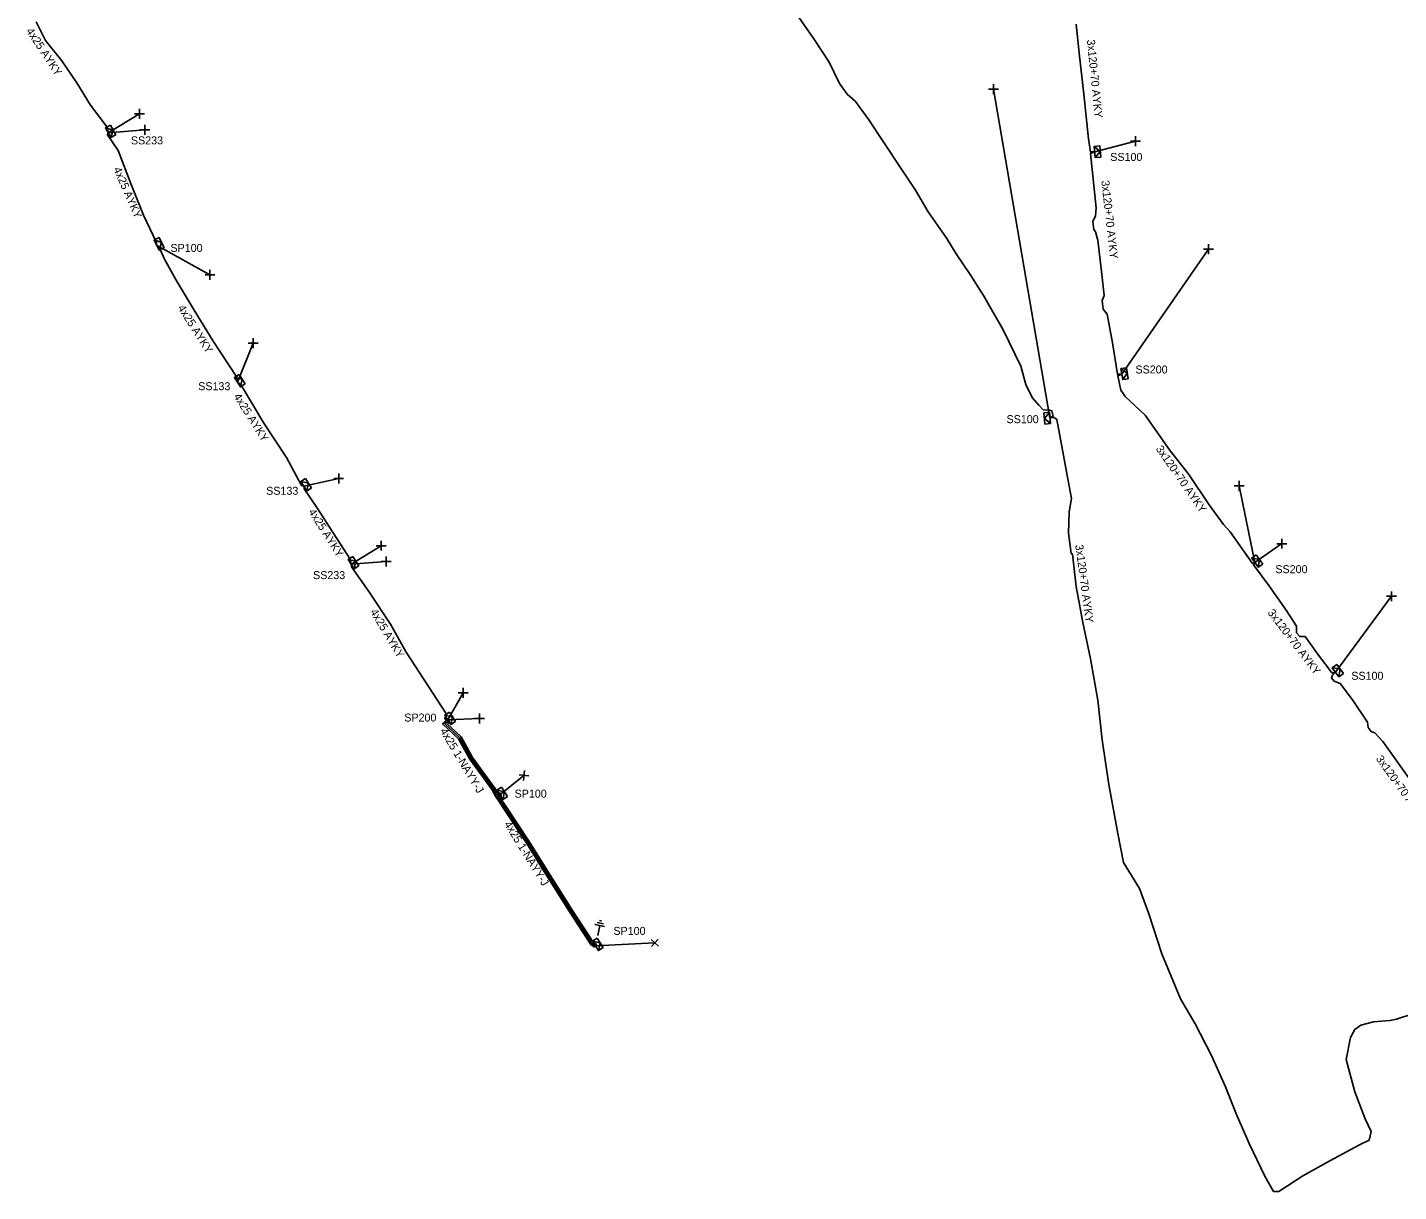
# Model space of a CAD drawing. Extents: x -763093 to -760976, y -1155572 to -1152009.
# Drawn here: x -762615.5 to -762444.1, y -1155221.8 to -1155076.3 of the extents above; entities that cross this region are included whole.
import ezdxf

# ---------------------------------------------------------------- set-up
doc = ezdxf.new("R2010")
doc.units = 0
for name, color, linetype in [('Vrstva 1', 7, 'Continuous'), ('Vrstva 14', 7, 'Continuous'), ('Vrstva 15', 7, 'Continuous'), ('Vrstva 20', 7, 'Continuous'), ('Vrstva 31', 7, 'Continuous'), ('Vrstva 33', 7, 'Continuous'), ('Vrstva 34', 7, 'Continuous'), ('Vrstva 5', 7, 'Continuous'), ('Vrstva 59', 7, 'Continuous'), ('Vrstva 6', 7, 'Continuous'), ('Vrstva 9', 7, 'Continuous')]:
    doc.layers.add(name, color=color, linetype=linetype)

# ---------------------------------------------------------------- blocks, each defined once
blk = doc.blocks.new('NN800')
at = {"layer": 'Vrstva 1'}
for points in [[(-0.44, 0.44), (0.44, -0.44)], [(-0.44, -0.44), (0.44, 0.44)]]:
    blk.add_lwpolyline(points, dxfattribs=at)
blk = doc.blocks.new('NN630')
at = {"layer": 'Vrstva 9'}
for points in [[(0, -0.7), (-0.7, 0)], [(-0.7, -0.7), (-0.7, 0), (0.7, 0), (0.7, -0.7)], [(-0.7, -0.7), (0.7, -0.7)], [(0, -0.7), (0.7, 0)]]:
    blk.add_lwpolyline(points, dxfattribs=at)
blk = doc.blocks.new('NN810')
at = {"layer": 'Vrstva 14'}
for points in [[(0, -0.64), (0, -1.89)], [(0.63, -1.89), (-0.62, -1.89)], [(0.39, -2.2), (-0.4, -2.2)], [(0, -2.52), (-0.12, -2.52)], [(0.14, -2.52), (0, -2.52)]]:
    blk.add_lwpolyline(points, dxfattribs=at)

msp = doc.modelspace()

# ---------------------------------------------------------------- linework, layer by layer
at = {"layer": 'Vrstva 20'}
for points in [[(-762556.36, -1155172.02), (-762556.52, -1155172.38), (-762556.7, -1155172.3), (-762556.93, -1155172.42), (-762557.4, -1155171.57), (-762560.19, -1155167.73), (-762561.58, -1155165.2), (-762562.83, -1155164.02), (-762563.58, -1155163.32), (-762563.16, -1155162.97), (-762563.15, -1155162.79), (-762562.75, -1155162.83), (-762562.78, -1155163.18), (-762562.97, -1155163.34), (-762562.56, -1155163.73), (-762561.26, -1155164.95), (-762559.85, -1155167.51), (-762557.06, -1155171.35), (-762556.76, -1155171.88), (-762556.71, -1155171.86)], [(-762544.58, -1155191.22), (-762545.05, -1155190.9), (-762547.77, -1155186.73), (-762550.88, -1155181.78), (-762553.07, -1155178.26), (-762556.01, -1155173.82), (-762556.61, -1155172.9), (-762556.87, -1155172.52), (-762556.64, -1155172.39), (-762556.64, -1155172.2), (-762556.24, -1155172.2), (-762556.24, -1155172.63), (-762556.29, -1155172.66), (-762556.28, -1155172.68), (-762555.67, -1155173.6), (-762552.74, -1155178.04), (-762550.54, -1155181.57), (-762547.44, -1155186.51), (-762544.76, -1155190.62), (-762544.35, -1155190.89)]]:
    msp.add_lwpolyline(points, close=True, dxfattribs=at)
at = {"layer": 'Vrstva 5'}
for points in [[(-762440.3, -1155198.87), (-762444.38, -1155200.23), (-762445.2, -1155200.39), (-762447.26, -1155200.56), (-762448.82, -1155200.98), (-762449.57, -1155201.5), (-762450.15, -1155202.53), (-762450.66, -1155205.25), (-762449.57, -1155209.31), (-762448.28, -1155212.66), (-762447.55, -1155214.26), (-762447.82, -1155215.36), (-762449, -1155215.91), (-762452.72, -1155217.93), (-762456.07, -1155219.81), (-762459.07, -1155221.77), (-762459.74, -1155221.74), (-762460.84, -1155219.85), (-762462.81, -1155215.76), (-762464.36, -1155212.15), (-762465.77, -1155208.66), (-762467.51, -1155204.77), (-762469.53, -1155200.8), (-762471.39, -1155197.67), (-762473.7, -1155192.06), (-762475.32, -1155187.04), (-762476.49, -1155183.9), (-762478.48, -1155180.65), (-762479.2, -1155177.03), (-762480.33, -1155170.91), (-762481.18, -1155165.31), (-762481.72, -1155160.37), (-762482.61, -1155155.2), (-762483.59, -1155150.64), (-762484.4, -1155146.14), (-762484.87, -1155142.1), (-762485.04, -1155142.02), (-762485.38, -1155139.5), (-762485.29, -1155136.83), (-762484.99, -1155135.17), (-762485.6, -1155131.81), (-762486.17, -1155128.88), (-762486.83, -1155125.28), (-762487.16, -1155125.05), (-762487.69, -1155125.08), (-762487.29, -1155124.87), (-762487.44, -1155124.21), (-762487.85, -1155124.07), (-762488.49, -1155124.1), (-762489.07, -1155123.5), (-762489.9, -1155122.54), (-762490.68, -1155120.9), (-762491.31, -1155118.62), (-762493.55, -1155114.08), (-762495.99, -1155109.77), (-762497.67, -1155107.14), (-762499.39, -1155104.57), (-762500.55, -1155102.67), (-762502.92, -1155099.32), (-762504.49, -1155096.63), (-762506.42, -1155093.74), (-762510.32, -1155087.83), (-762512, -1155085.56), (-762513.01, -1155084.64), (-762514, -1155083.29), (-762515.27, -1155080.61), (-762517.19, -1155077.69), (-762519.67, -1155074.14)], [(-762614.37, -1155075.57), (-762613.2, -1155077.93), (-762611.17, -1155080.46), (-762609.28, -1155083.2), (-762607.58, -1155085.98), (-762605.5, -1155088.73), (-762605.36, -1155089.44), (-762605.45, -1155089.72), (-762604.11, -1155091.68), (-762602.49, -1155095.92), (-762600.94, -1155099.73), (-762599.33, -1155103.18), (-762599.31, -1155103.48), (-762598.86, -1155104.05), (-762598.33, -1155105.25), (-762596.85, -1155107.87), (-762594.6, -1155111.6), (-762592.25, -1155115.5), (-762589.3, -1155120), (-762589.21, -1155120.62), (-762588.75, -1155120.99), (-762585.91, -1155125.73), (-762583.08, -1155130.03), (-762581.2, -1155133.52), (-762580.92, -1155133.62), (-762580.88, -1155133.96), (-762579.31, -1155136.29), (-762577.27, -1155139.43), (-762575.13, -1155142.75), (-762574.99, -1155143.36), (-762574.94, -1155143.69), (-762572.79, -1155146.79), (-762570.07, -1155150.85), (-762568.12, -1155154.36), (-762563.09, -1155162.11), (-762563.3, -1155162.67), (-762562.94, -1155162.81)], [(-762452, -1155156.87), (-762452.41, -1155157), (-762454.12, -1155154.73), (-762455.8, -1155152.38), (-762456.47, -1155152.42), (-762456.87, -1155151.96), (-762456.9, -1155151.12), (-762458.15, -1155149.1), (-762460.34, -1155146.01), (-762462.24, -1155143.44), (-762462.07, -1155143.17), (-762462.36, -1155143.28), (-762465.15, -1155139.3), (-762466.01, -1155138.41), (-762467.8, -1155135.94), (-762470.34, -1155132.16), (-762472.74, -1155129.06), (-762475.78, -1155124.73), (-762478.24, -1155122.46), (-762478.83, -1155121.6), (-762479.21, -1155119.82), (-762478.71, -1155119.61), (-762479.25, -1155119.62), (-762479.85, -1155115.7), (-762480.54, -1155112.1), (-762481.04, -1155111.49), (-762481.18, -1155110.43), (-762480.91, -1155109.77), (-762481.24, -1155106.79), (-762481.69, -1155102.88), (-762482, -1155101.82), (-762482.22, -1155101.52), (-762482.31, -1155100.55), (-762482.01, -1155099.84), (-762481.9, -1155098.84), (-762482.62, -1155092.05), (-762482.09, -1155091.85), (-762482.64, -1155091.85), (-762482.88, -1155090.2), (-762483.46, -1155084.63), (-762484.04, -1155079.48), (-762484.39, -1155075.89)], [(-762452, -1155156.87), (-762452.4, -1155157.22), (-762452.5, -1155157.55), (-762452.19, -1155158), (-762451.44, -1155158.29), (-762449.88, -1155160.3), (-762448, -1155163.1), (-762447.93, -1155163.76), (-762447.55, -1155164.29), (-762447.11, -1155164.46), (-762446.11, -1155165.54), (-762442.69, -1155170.32), (-762439.62, -1155174.75), (-762438.62, -1155175.88), (-762438.38, -1155175.68)], [(-762562.95, -1155162.81), (-762562.97, -1155163.08), (-762563.28, -1155163.33), (-762562.69, -1155163.88), (-762561.42, -1155165.08), (-762560.02, -1155167.62), (-762557.23, -1155171.46), (-762556.84, -1155172.15), (-762556.71, -1155172.08), (-762556.44, -1155172.2), (-762556.44, -1155172.51), (-762556.58, -1155172.59), (-762556.45, -1155172.79), (-762555.84, -1155173.71), (-762552.91, -1155178.15), (-762550.71, -1155181.68), (-762547.61, -1155186.62), (-762544.91, -1155190.76), (-762544.47, -1155191.06)]]:
    msp.add_lwpolyline(points, dxfattribs=at)
at = {"layer": 'Vrstva 59'}
for points in [[(-762487.69, -1155125.08), (-762494.75, -1155084)], [(-762605.36, -1155089.44), (-762601.44, -1155087.1)], [(-762605.36, -1155089.44), (-762600.79, -1155089.07)], [(-762482.09, -1155091.85), (-762477, -1155090.5)], [(-762599.31, -1155103.48), (-762592.64, -1155107.22)], [(-762478.71, -1155119.61), (-762467.88, -1155104)], [(-762589.21, -1155120.62), (-762587.25, -1155115.73)], [(-762580.92, -1155133.62), (-762576.56, -1155132.64)], [(-762462.07, -1155143.17), (-762464.03, -1155133.58)], [(-762574.99, -1155143.36), (-762571.24, -1155141.05)], [(-762462.07, -1155143.17), (-762458.73, -1155140.79)], [(-762574.99, -1155143.36), (-762570.62, -1155143.03)], [(-762452, -1155156.87), (-762445, -1155147.38)], [(-762562.94, -1155162.81), (-762561.02, -1155159.44)], [(-762562.94, -1155162.81), (-762558.95, -1155162.65)], [(-762556.44, -1155172.2), (-762553.41, -1155169.76)], [(-762544.47, -1155191.06), (-762537.04, -1155190.7)]]:
    msp.add_lwpolyline(points, dxfattribs=at)

# ---------------------------------------------------------------- block references
at = {"layer": 'Vrstva 15', "rotation": 168.54964677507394}
msp.add_blockref('NN810', (-762544.32, -1155190.39), dxfattribs=at)
at = {"layer": 'Vrstva 31'}
for p, rotation in [((-762605.36, -1155089.44), 118.15342155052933), ((-762482.09, -1155091.85), 95.5048249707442), ((-762599.31, -1155103.48), 115.66805267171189), ((-762478.71, -1155119.61), 99.44618602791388), ((-762589.21, -1155120.62), 122.34904446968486), ((-762487.69, -1155125.08), -84.08791565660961), ((-762580.92, -1155133.62), 121.53974072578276), ((-762574.99, -1155143.36), 122.31663886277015), ((-762462.07, -1155143.17), 125.07625826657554), ((-762452, -1155156.87), 126.0426221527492), ((-762562.94, -1155162.81), 122.30344995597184), ((-762556.44, -1155172.2), 122.73549698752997), ((-762544.47, -1155191.06), 122.93412893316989)]:
    msp.add_blockref('NN630', p, dxfattribs=dict(at, rotation=rotation))
at = {"layer": 'Vrstva 34'}
for p, rotation in [((-762494.75, -1155084), 45), ((-762601.44, -1155087.1), 45.00000009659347), ((-762600.79, -1155089.07), 45), ((-762477, -1155090.5), 45), ((-762467.88, -1155104), 45), ((-762592.64, -1155107.22), 44.99999995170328), ((-762587.25, -1155115.73), 45), ((-762576.56, -1155132.64), 45), ((-762464.03, -1155133.58), 45), ((-762458.73, -1155140.8), 45), ((-762571.24, -1155141.05), 45), ((-762570.62, -1155143.03), 45), ((-762445, -1155147.38), 45), ((-762561.02, -1155159.44), 45), ((-762558.95, -1155162.65), 45), ((-762553.41, -1155169.76), 38.8554172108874), ((-762537.04, -1155190.7), 2.7527198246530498)]:
    msp.add_blockref('NN800', p, dxfattribs=dict(at, rotation=rotation))

# ---------------------------------------------------------------- texts
at = {"layer": 'Vrstva 33'}
for s, p in [('SS233', (-762602.52, -1155090.9)), ('SS100', (-762480.15, -1155092.97)), ('SP100', (-762597.58, -1155104.34)), ('SS200', (-762477, -1155119.53)), ('SS133', (-762594.11, -1155121.62)), ('SS100', (-762493.11, -1155125.74)), ('SS133', (-762585.62, -1155134.69)), ('SS200', (-762459.52, -1155144.49)), ('SS233', (-762579.76, -1155145.23)), ('SS100', (-762450.03, -1155157.81)), ('SP200', (-762568.36, -1155163.03)), ('SP100', (-762554.58, -1155172.54)), ('SP100', (-762542.23, -1155189.69))]:
    msp.add_text(s, height=1, dxfattribs=at).set_placement(p)
at = {"layer": 'Vrstva 6'}
for s, rotation, p in [('4x25 AYKY', 303.439, (-762615.66, -1155076.73)), ('3x120+70 AYKY', 275.702, (-762483.07, -1155077.84)), ('4x25 AYKY', 293.388, (-762604.73, -1155093.97)), ('3x120+70 AYKY', 276.387, (-762481.27, -1155095.45)), ('4x25 AYKY', 302.402, (-762596.72, -1155111.34)), ('4x25 AYKY', 302.352, (-762589.74, -1155122.39)), ('3x120+70 AYKY', 304.936, (-762474.51, -1155128.95)), ('4x25 AYKY', 302.402, (-762580.39, -1155136.81)), ('3x120+70 AYKY', 277.667, (-762484.53, -1155140.97)), ('4x25 AYKY', 300.814, (-762572.67, -1155149.31)), ('3x120+70 AYKY', 307.264, (-762460.55, -1155149.44)), ('4x25 1-NAYY-J', 300.945, (-762563.95, -1155164.2)), ('3x120+70 AYKY', 305.773, (-762447.01, -1155167.69)), ('4x25 1-NAYY-J', 301.841, (-762555.94, -1155175.85))]:
    msp.add_text(s, height=1, rotation=rotation, dxfattribs=at).set_placement(p)

doc.saveas('drawing.dxf')
